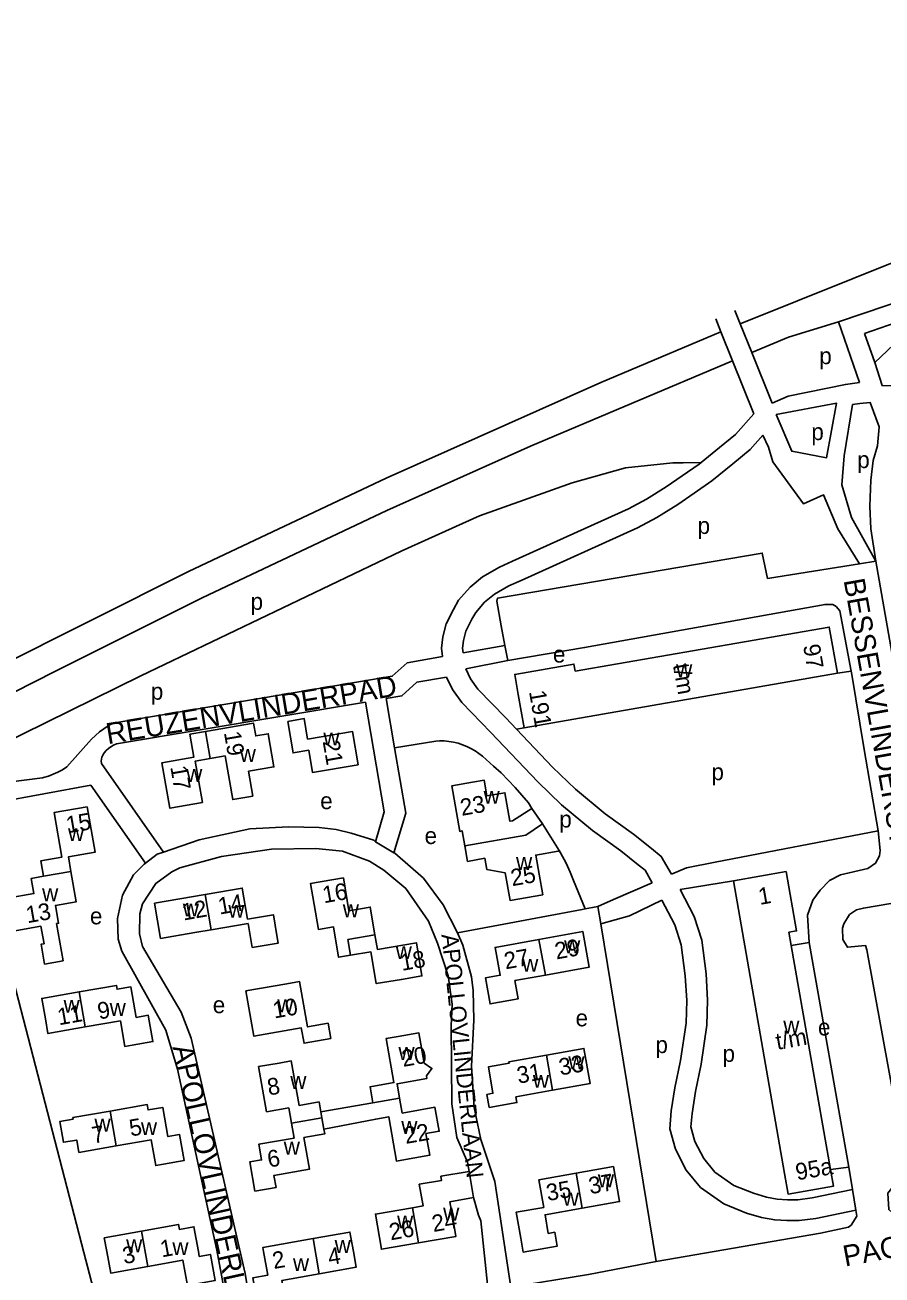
# Model space of a CAD drawing. Extents: x 162883 to 165538, y 383986 to 385172.
# Drawn here: x 164067.6 to 164272, y 384744.4 to 385042.6 of the extents above; entities that cross this region are included whole.
import ezdxf

# ---------------------------------------------------------------- set-up
doc = ezdxf.new("R2010")
doc.units = 0
for name, color, linetype in [('BLT_Basislijn', 7, 'Continuous'), ('BLT_Bebouwing', 7, 'Continuous'), ('BLT_Centroide', 7, 'Continuous'), ('BLT_Huisnummer', 7, 'Continuous'), ('BLT_Huisnummer_reeks', 7, 'Continuous'), ('BLT_Onderverdeling_panden', 7, 'Continuous'), ('BLT_Straatnaam', 7, 'Continuous'), ('BLT_Straatnaam_verkleind', 7, 'Continuous')]:
    doc.layers.add(name, color=color, linetype=linetype)

msp = doc.modelspace()

# ---------------------------------------------------------------- linework, layer by layer
at = {"layer": 'BLT_Basislijn'}
for p, q in [((164283.76, 384989.59), (164238.23, 384971.28)), ((164261.66, 384971.76), (164292.03, 384982.1)), ((164267.9, 384969), (164293.76, 384977.99)), ((164236.95, 384974.46), (164238.23, 384971.28)), ((164232.37, 384972.46), (164233.62, 384969.34)), ((164238.23, 384971.28), (164241, 384964.41)), ((164261.66, 384971.76), (164266.65, 384957.28)), ((164233.62, 384969.34), (164236.39, 384962.47)), ((164267.9, 384969), (164270.29, 384962.05)), ((164241, 384964.41), (164245.86, 384952.35)), ((164236.39, 384962.47), (164241.49, 384949.82)), ((164249.61, 384954.04), (164245.86, 384952.35)), ((164224.6, 384938.13), (164228.89, 384938.23)), ((164181.18, 384899.24), (164182.09, 384894.57)), ((164182.09, 384894.57), (164182.8, 384890.95)), ((164182.8, 384890.95), (164172.75, 384888.98)), ((164261.38, 384887.91), (164264.67, 384888.42)), ((164089.39, 384871.05), (164148.83, 384881.06)), ((164153.76, 384881.89), (164155.76, 384870.14)), ((164186.63, 384874.92), (164184.82, 384874.62)), ((164083.46, 384872.22), (164077.55, 384865.57)), ((164165.57, 384871.74), (164155.76, 384870.14)), ((164085.84, 384866.36), (164100.62, 384845.25)), ((164083.31, 384861.25), (164054.09, 384855.8)), ((164071.72, 384862.98), (164063.65, 384861.95)), ((164083.31, 384861.25), (164096.35, 384842.63)), ((164054.09, 384855.8), (164081.63, 384749.74)), ((164099.12, 384844.73), (164100.62, 384845.25)), ((164151.18, 384847.74), (164155.61, 384845.09)), ((164155.61, 384845.09), (164155.77, 384845)), ((164096.35, 384842.63), (164095.97, 384842.34)), ((164099.12, 384844.73), (164096.35, 384842.63)), ((164198.45, 384838.51), (164201.18, 384831.69)), ((164236.57, 384838.38), (164223.85, 384836.3)), ((164200.54, 384831.57), (164170.73, 384825.96)), ((164200.54, 384831.57), (164201.18, 384831.69)), ((164201.18, 384831.69), (164202.97, 384832.01)), ((164202.97, 384832.01), (164204.28, 384832.24)), ((164204.95, 384828.17), (164204.28, 384832.24)), ((164218.19, 384747.63), (164204.95, 384828.17)), ((164254.66, 384823.68), (164250.38, 384822.96)), ((164254.66, 384823.68), (164264.11, 384770.12)), ((164264.11, 384770.12), (164259.78, 384769.55)), ((164081.63, 384749.74), (164088.15, 384724.64))]:
    msp.add_line(p, q, dxfattribs=at)
for points in [[(164490.02, 385042.56), (164488.13, 385042.29), (164422.4, 385021.48), (164377.6, 385005.76), (164289.97, 384972.55), (164276.26, 384967.72), (164270.29, 384962.05)], [(164261.66, 384971.76), (164249.74, 384968.11), (164241, 384964.41)], [(164233.62, 384969.34), (164204.95, 384957.3), (164153.73, 384934.44)], [(164270.29, 384962.05), (164272.06, 384956.53), (164277.96, 384956.41), (164284.23, 384957.02), (164288.93, 384957.86), (164294.36, 384959.07), (164300.27, 384960.39), (164302.8, 384961), (164305.69, 384961.96), (164308.34, 384963.17), (164315.2, 384968.2)], [(164236.39, 384962.47), (164188.18, 384942.07), (164153.89, 384926.74)], [(164249.61, 384954.04), (164263.32, 384956.83), (164266.65, 384957.28)], [(164266.73, 384952.25), (164269.25, 384952.47), (164271.36, 384946.68), (164270.94, 384942.16), (164269.95, 384938.64), (164269.39, 384933.98), (164269.11, 384927.77), (164269.39, 384922.41), (164270.57, 384914.65)], [(164228.89, 384938.23), (164233.27, 384941.76), (164237.09, 384944.88), (164241.49, 384949.82)], [(164270.57, 384914.65), (164264.73, 384925.09), (164262.48, 384932.85), (164263.04, 384939.77), (164265.02, 384952.01)], [(164265.02, 384952.01), (164266.73, 384952.25)], [(164172.1, 384892.8), (164171.98, 384893.88), (164172.18, 384895.71), (164172.78, 384897.93), (164174.21, 384900.79), (164175.14, 384902.45), (164177.24, 384904.87), (164179.58, 384906.78), (164183.02, 384908.78), (164185.92, 384910.05), (164213.74, 384922.64), (164218.34, 384925.1), (164223.32, 384928.19), (164227.24, 384930.89), (164231.41, 384933.84), (164236.43, 384937.87), (164240.56, 384941.26), (164243.63, 384944.7)], [(164243.63, 384944.7), (164244.99, 384941.88), (164245.97, 384938.35), (164253.31, 384928.33), (164258.1, 384930.45), (164261.49, 384922.41), (164266.7, 384914.03)], [(163832.96, 384744.27), (163844.99, 384751.02), (164038.65, 384858.43), (164038.88, 384858.81), (164039.72, 384859.01), (164061.27, 384870.58), (164095.24, 384887.32), (164157.3, 384917.02), (164176.04, 384925.47), (164198.09, 384933.36), (164210.88, 384936.92), (164222.14, 384938.13), (164224.6, 384938.13)], [(164167.16, 384891.92), (164166.96, 384893.88), (164167.24, 384896.64), (164168.09, 384899.72), (164169.79, 384903.14), (164171.03, 384905.34), (164173.75, 384908.47), (164176.72, 384910.9), (164180.75, 384913.24), (164183.88, 384914.62), (164211.52, 384927.12), (164215.84, 384929.44), (164220.58, 384932.38), (164224.38, 384934.99), (164228.4, 384937.83), (164228.89, 384938.23)], [(164153.73, 384934.44), (164106.58, 384912.17), (164059.88, 384888.8), (164044.54, 384881.09)], [(164153.89, 384926.74), (164109.86, 384905.93), (164074.69, 384888.33), (164050.32, 384876.05)], [(164181.18, 384899.24), (164180.15, 384905.12), (164180.31, 384905.87), (164243.47, 384916.58), (164244.74, 384910.51)], [(164244.74, 384910.51), (164266.7, 384914.03)], [(164266.7, 384914.03), (164270.57, 384914.65)], [(164277.93, 384872.45), (164270.57, 384914.65)], [(164264.67, 384888.42), (164261.94, 384902.78), (164261.08, 384903.83), (164260.31, 384904.29), (164258.44, 384904.34), (164201.09, 384894.06), (164182.8, 384890.95)], [(164172.1, 384892.8), (164182.09, 384894.57)], [(164088.56, 384875.98), (164155.21, 384887.2), (164158.76, 384890.43), (164167.16, 384891.92)], [(164153.76, 384881.89), (164157.49, 384882.51), (164161.06, 384885.76), (164168.15, 384887.02)], [(164168.15, 384887.02), (164169.54, 384884.07), (164171.77, 384880.94), (164178.69, 384873.82), (164189.9, 384862), (164195.59, 384856.5), (164202.93, 384850.39), (164209.73, 384845.58), (164213.87, 384842.23), (164215.51, 384840.92), (164217.23, 384837.96)], [(164172.75, 384888.98), (164173.87, 384886.61), (164175.62, 384884.15), (164182.29, 384877.28), (164184.82, 384874.62)], [(164267.82, 384869.77), (164264.74, 384888.08), (164264.67, 384888.42)], [(164148.83, 384881.06), (164153.3, 384854.86), (164151.18, 384847.74)], [(164088.56, 384875.98), (164087.45, 384875.36), (164086.38, 384874.67), (164085.36, 384873.92), (164084.39, 384873.1), (164083.46, 384872.22)], [(164184.82, 384874.62), (164193.45, 384865.52), (164198.93, 384860.23), (164205.98, 384854.36), (164212.75, 384849.57), (164217.01, 384846.13), (164219.36, 384844.24), (164221.85, 384839.97)], [(164089.39, 384871.05), (164088.72, 384870.76), (164088.08, 384870.39), (164087.49, 384869.96), (164086.95, 384869.47), (164086.47, 384868.93), (164086.38, 384868.81)], [(164155.76, 384870.14), (164158.42, 384854.56), (164155.61, 384845.09)], [(164177.56, 384867.37), (164176.74, 384868.12), (164175.86, 384868.8), (164174.94, 384869.43), (164173.98, 384869.99), (164172.98, 384870.47), (164171.95, 384870.88), (164170.89, 384871.22), (164169.81, 384871.48), (164168.71, 384871.66), (164167.61, 384871.76), (164166.5, 384871.79), (164165.57, 384871.74)], [(164271.09, 384850.3), (164267.82, 384869.77)], [(164086.38, 384868.81), (164086.12, 384868.39), (164085.92, 384867.94), (164085.81, 384867.46), (164085.77, 384866.97), (164085.81, 384866.47), (164085.84, 384866.36)], [(164177.56, 384867.37), (164179.38, 384865.78), (164181.16, 384864.13), (164182.88, 384862.43), (164184.54, 384860.67), (164186.14, 384858.85), (164187.69, 384856.99), (164188.47, 384855.69)], [(164077.55, 384865.57), (164076.51, 384864.92), (164075.43, 384864.34), (164074.31, 384863.84), (164073.16, 384863.4), (164071.98, 384863.05), (164071.72, 384862.98)], [(164100.62, 384845.25), (164109.16, 384848.22), (164121.25, 384850.78), (164130.42, 384851.26), (164137.74, 384851.14), (164141.78, 384850.62), (164145.43, 384849.75), (164150.76, 384848.08), (164151.18, 384847.74)], [(164232.22, 384842.82), (164271.09, 384850.3)], [(164254.66, 384823.68), (164254.29, 384830.21), (164255.52, 384833.76), (164257.26, 384836.18), (164259.49, 384838.45), (164262.1, 384839.82), (164268.62, 384841.31), (164270.47, 384842.58), (164271.42, 384844.33), (164271.58, 384845.67), (164271.09, 384850.3)], [(164173.52, 384769.06), (164173.14, 384771.32), (164170.63, 384777.21), (164169.37, 384785.24), (164169.21, 384803.85), (164169.45, 384808.94), (164168.57, 384815.72), (164165.99, 384823.55), (164163.88, 384828.74), (164158.47, 384836.54), (164153.16, 384840.98), (164149.79, 384843.12), (164143.36, 384845.45), (164136.93, 384846.08), (164126.4, 384845.93), (164114.47, 384844.18), (164104.55, 384841.47), (164102.57, 384840.52), (164098.82, 384837.78), (164095.64, 384832.88), (164095, 384830.49), (164094.89, 384825.75), (164095.64, 384822.7), (164104.8, 384807.05), (164107.25, 384800.9), (164120.14, 384744.7), (164122.44, 384730.7)], [(164195, 384845.62), (164195.32, 384845.05), (164196.65, 384842.65), (164197.65, 384840.44), (164198.45, 384838.51)], [(164095.97, 384842.34), (164093.47, 384839.82), (164090.83, 384834.95), (164089.67, 384829.38), (164089.81, 384824.45), (164090.64, 384821.59), (164101.2, 384802.81), (164103.99, 384793.49), (164113.36, 384750.3), (164117.16, 384729.76), (164088.15, 384724.64)], [(164170.73, 384825.96), (164167.31, 384832.71), (164162.62, 384839.05), (164155.77, 384845)], [(164221.85, 384839.97), (164225.38, 384841.5), (164232.22, 384842.82)], [(164204.28, 384832.24), (164207.96, 384833.94), (164217.23, 384837.96)], [(164223.85, 384836.3), (164227.23, 384829.87), (164229.05, 384824.24), (164230.09, 384816.19), (164230.44, 384809.94), (164230.27, 384803.98), (164228.89, 384794.69), (164227.55, 384788.13), (164226.73, 384782.89), (164226.44, 384779.73), (164227.42, 384776.22), (164229.54, 384772.14), (164232.18, 384768.91), (164236.69, 384765.75), (164241.36, 384763.88), (164244.47, 384762.95), (164247.04, 384762.49), (164249.51, 384762.34), (164251.95, 384762.34), (164255.39, 384762.81), (164264.98, 384764.78)], [(164219.51, 384833.82), (164211.82, 384830.07), (164204.95, 384828.17)], [(164219.51, 384833.82), (164222.6, 384827.93), (164224.15, 384823.14), (164225.11, 384815.73), (164225.44, 384809.88), (164225.28, 384804.42), (164223.96, 384795.56), (164222.62, 384789.01), (164221.76, 384783.5), (164221.38, 384779.27), (164222.75, 384774.38), (164225.34, 384769.38), (164228.74, 384765.21), (164234.3, 384761.32), (164239.71, 384759.16), (164243.31, 384758.07), (164246.45, 384757.52), (164249.36, 384757.34), (164252.29, 384757.34), (164256.24, 384757.88), (164265.78, 384759.84)], [(164283.48, 384834.6), (164267.61, 384831.89), (164265.95, 384831.5), (164264.26, 384830.34), (164262.93, 384828.17), (164262.65, 384827.11), (164262.71, 384824.37), (164263.8, 384822.54), (164268.11, 384822.94), (164268.43, 384821.96), (164277.4, 384772.74), (164278.33, 384766.16), (164274.67, 384765.52), (164273.43, 384763.9), (164273.65, 384759.96), (164275.72, 384758.07), (164277.4, 384757.88), (164284.57, 384759.39)], [(164218.19, 384747.63), (164202, 384744.49), (164183.49, 384741.49), (164179.63, 384766.7), (164176.36, 384776.66), (164174.75, 384784.35), (164174.11, 384794.16), (164174.69, 384805.19), (164174.5, 384812.21), (164174.11, 384815.48), (164172.03, 384823.03), (164170.73, 384825.96)], [(164264.98, 384764.78), (164264.11, 384770.12)], [(164265.78, 384759.84), (164264.98, 384764.78)], [(164178.07, 384740.58), (164176.29, 384757.32), (164175.74, 384758.62), (164174.58, 384762.82)], [(164218.19, 384747.63), (164257.4, 384754.38), (164264.02, 384755.75), (164264.68, 384756.27), (164266.01, 384758.43), (164265.78, 384759.84)]]:
    msp.add_lwpolyline(points, dxfattribs=at)
msp.add_lwpolyline([(164246.82, 384949.64), (164250.49, 384940.89), (164258.81, 384939.34), (164261.21, 384952.33)], close=True, dxfattribs=at)
at = {"layer": 'BLT_Bebouwing'}
for p, q in [((164110.63, 384874.06), (164106.9, 384873.41)), ((164188.47, 384855.69), (164191.06, 384852.01)), ((164191.06, 384852.01), (164195, 384845.62)), ((164259.78, 384769.55), (164250.38, 384822.96)), ((164138.17, 384783.26), (164150.57, 384785.42)), ((164174.58, 384762.82), (164173.52, 384769.06))]:
    msp.add_line(p, q, dxfattribs=at)
for points in [[(164186.63, 384874.92), (164185.23, 384882.83), (164184.41, 384887.63), (164198.55, 384890.09), (164198.84, 384888.42), (164259.45, 384898.95), (164261.38, 384887.91)], [(164186.63, 384874.92), (164261.38, 384887.91)], [(164121.93, 384858.6), (164120.9, 384864.54), (164126.97, 384865.59), (164125.59, 384873.5), (164122.63, 384872.99), (164122.09, 384876.05), (164110.63, 384874.06)], [(164130.26, 384876.43), (164134.18, 384877.09), (164135, 384872.21), (164145.71, 384874.02), (164147.05, 384866.09), (164136.15, 384864.26), (164135.26, 384869.54), (164131.52, 384868.91), (164130.26, 384876.43)], [(164106.9, 384873.41), (164107.86, 384867.91), (164100.26, 384866.59), (164102.15, 384855.73), (164109.92, 384857.09), (164108.2, 384866.96), (164111.76, 384867.58)], [(164111.76, 384867.58), (164115.31, 384868.2), (164117.13, 384857.77), (164121.93, 384858.6)], [(164172.52, 384846.75), (164171.9, 384850.3), (164171.3, 384850.2), (164169.4, 384861.04), (164174.33, 384861.9), (164177.14, 384862.39), (164177.78, 384858.68), (164182.08, 384859.43), (164183.27, 384852.62), (164183.91, 384852.73), (164188.47, 384855.69)], [(164072.02, 384839.5), (164071.37, 384843.2), (164076.38, 384844.08), (164074.52, 384854.68), (164082.39, 384856.05), (164084.29, 384845.23), (164077.94, 384844.12), (164078.55, 384840.65)], [(164177.3, 384843.77), (164173.17, 384843.05), (164172.52, 384846.75)], [(164195, 384845.62), (164194.8, 384845.5), (164189.42, 384844.56), (164190.21, 384840.01), (164191.08, 384835.08), (164183.31, 384833.73), (164182.17, 384840.27), (164177.77, 384841.09), (164177.3, 384843.77)], [(164078.55, 384840.65), (164079.82, 384833.41), (164074.84, 384832.54), (164075.59, 384828.29), (164075.13, 384828.21), (164076.68, 384819.34), (164072.23, 384818.56), (164071.4, 384823.28), (164072.11, 384823.4), (164071.39, 384827.56), (164064.75, 384826.4), (164063.38, 384834.25), (164069.71, 384835.36), (164069.07, 384838.99), (164072.02, 384839.5)], [(164236.57, 384838.38), (164249.15, 384840.6), (164251.64, 384826.44), (164249.82, 384826.13), (164250.38, 384822.96)], [(164112, 384826.72), (164120.81, 384828.22), (164121.78, 384822.5), (164127.99, 384823.56), (164127.67, 384825.38), (164126.83, 384830.31), (164120.68, 384829.26), (164119.4, 384836.69), (164110.56, 384835.18)], [(164145.26, 384820.64), (164142.4, 384820.16), (164141.18, 384827.41), (164137.56, 384826.8), (164136.55, 384832.79), (164135.71, 384837.77), (164143.55, 384839.09), (164144.86, 384831.27), (164149.95, 384832.13), (164151.06, 384825.54)], [(164259.78, 384769.55), (164260.48, 384765.57), (164249.64, 384763.66), (164248.78, 384768.59), (164236.57, 384838.38)], [(164110.56, 384835.18), (164098.45, 384833.11)], [(164098.45, 384833.11), (164099.87, 384824.64)], [(164099.87, 384824.64), (164108.08, 384826.04), (164112, 384826.72)], [(164151.06, 384825.54), (164151.65, 384822.06), (164160.96, 384823.62), (164162.29, 384815.72), (164157.36, 384814.89), (164151.38, 384813.88), (164150.11, 384821.46), (164145.26, 384820.64)], [(164190.19, 384824.41), (164179.74, 384822.5), (164180.95, 384815.87), (164177.43, 384815.23), (164178.55, 384809.05), (164185.26, 384810.27), (164184.47, 384814.59), (164191.74, 384815.92)], [(164191.74, 384815.92), (164202.19, 384817.82), (164200.64, 384826.32), (164190.19, 384824.41)], [(164081.95, 384803.54), (164090.32, 384805), (164091.38, 384798.9), (164093.16, 384799.21), (164098.08, 384800.07), (164096.99, 384806.33), (164094.11, 384805.83), (164092.84, 384813.1), (164089.54, 384812.52), (164089.38, 384813.47), (164080.48, 384811.91)], [(164140.54, 384800.79), (164139.9, 384804.43), (164134.98, 384803.57), (164133.08, 384814.38), (164130.07, 384813.85), (164120.27, 384812.13), (164122.17, 384801.31), (164133.49, 384803.31), (164134.14, 384799.66), (164140.54, 384800.79)], [(164080.48, 384811.91), (164071.59, 384810.36), (164072.45, 384805.45), (164073.06, 384801.98), (164081.95, 384803.54)], [(164150.57, 384785.42), (164149.9, 384789.26), (164155.59, 384790.26), (164153.74, 384800.77), (164156.62, 384801.28), (164161.54, 384802.14), (164162.81, 384794.91), (164164.65, 384793.66), (164163.34, 384791.9), (164163.46, 384791.26), (164156.35, 384790.01), (164156.96, 384786.54)], [(164193.46, 384788.43), (164202.41, 384790.03), (164200.92, 384798.43), (164191.97, 384796.83)], [(164131.14, 384780.57), (164130.49, 384784.23), (164125.2, 384783.3), (164123.31, 384794.08), (164128.21, 384794.94), (164131.1, 384795.45), (164132.97, 384784.83), (164137.75, 384785.67), (164138.17, 384783.26)], [(164191.97, 384796.83), (164183.02, 384795.24), (164183.08, 384794.9), (164178.13, 384794.02), (164179.21, 384787.72), (164177.77, 384787.46), (164178.32, 384784.36), (164184.95, 384785.51), (164184.71, 384786.87), (164193.46, 384788.43)], [(164156.96, 384786.54), (164157.58, 384783), (164165.39, 384784.37), (164166.39, 384778.66), (164163.22, 384778.11), (164164.12, 384772.95), (164159.2, 384772.09), (164156.2, 384771.56), (164154.34, 384782.12), (164151.25, 384781.58), (164138.89, 384779.15)], [(164087.86, 384783.47), (164078.99, 384781.94), (164079.05, 384781.57), (164075.89, 384781.02), (164076.75, 384776.02), (164079.92, 384776.56), (164080.42, 384773.63), (164089.3, 384775.16)], [(164089.3, 384775.16), (164097.71, 384776.61), (164098.76, 384770.48), (164100.6, 384770.8), (164105.53, 384771.65), (164104.46, 384777.86), (164101.66, 384777.38), (164100.42, 384784.36), (164096.96, 384783.76), (164096.74, 384785.01), (164087.86, 384783.47)], [(164138.89, 384779.15), (164139.09, 384778.02), (164134.12, 384777.15), (164135.45, 384769.6), (164126.97, 384768.11), (164127.47, 384765.25), (164122.43, 384764.37), (164121.21, 384771.34), (164124, 384771.83), (164123.35, 384775.58), (164131.76, 384777.05), (164131.14, 384780.57)], [(164173.52, 384769.06), (164166.81, 384767.92), (164166.97, 384766.94), (164161.65, 384766.01), (164162.53, 384760.84), (164160.06, 384760.42)], [(164185.84, 384753.14), (164184.74, 384759.33), (164191.35, 384760.5), (164190.18, 384767.11), (164199.06, 384768.68)], [(164199.06, 384768.68), (164207.94, 384770.25), (164209.42, 384761.9), (164200.54, 384760.32)], [(164161.48, 384752.04), (164170.36, 384753.55), (164169.62, 384757.91), (164168.94, 384761.86), (164174.58, 384762.82)], [(164160.06, 384760.42), (164151.19, 384758.92), (164152.61, 384750.53), (164161.48, 384752.04)], [(164200.54, 384760.32), (164191.64, 384758.75), (164192.43, 384754.31)], [(164108.94, 384750), (164107.87, 384755.87), (164104.43, 384755.24), (164104.21, 384756.43), (164095.36, 384754.82)], [(164095.36, 384754.82), (164086.5, 384753.2), (164087.09, 384750)], [(164136.32, 384753.07), (164124.32, 384750.96), (164124.49, 384750)], [(164145.92, 384750), (164145.11, 384754.61), (164136.32, 384753.07)], [(164192.43, 384754.31), (164193.98, 384754.58), (164194.57, 384751.28), (164186.42, 384749.84), (164185.84, 384753.14)], [(164096.89, 384746.43), (164088.02, 384744.81), (164087.09, 384750)], [(164108.94, 384750), (164109.14, 384748.81), (164111.8, 384749.3), (164112.94, 384743.05), (164106.32, 384741.84), (164105.2, 384747.94), (164096.89, 384746.43)], [(164124.49, 384750), (164125.5, 384744.36), (164121.94, 384743.73), (164123.03, 384737.53), (164129.65, 384738.69), (164128.88, 384743.09), (164137.78, 384744.66)], [(164137.78, 384744.66), (164146.58, 384746.21), (164145.92, 384750)]]:
    msp.add_lwpolyline(points, dxfattribs=at)
at = {"layer": 'BLT_Onderverdeling_panden'}
for p, q in [((164111.76, 384867.58), (164110.63, 384874.06)), ((164072.02, 384839.5), (164078.55, 384840.65)), ((164110.56, 384835.18), (164112, 384826.72)), ((164190.19, 384824.41), (164191.74, 384815.92)), ((164080.48, 384811.91), (164081.95, 384803.54)), ((164191.97, 384796.83), (164193.46, 384788.43)), ((164150.57, 384785.42), (164156.96, 384786.54)), ((164087.86, 384783.47), (164089.3, 384775.16)), ((164138.17, 384783.26), (164138.42, 384781.85)), ((164138.42, 384781.85), (164131.14, 384780.57)), ((164138.42, 384781.85), (164138.89, 384779.15)), ((164199.06, 384768.68), (164200.54, 384760.32)), ((164161.48, 384752.04), (164160.06, 384760.42)), ((164095.36, 384754.82), (164096.89, 384746.43)), ((164136.32, 384753.07), (164137.78, 384744.66))]:
    msp.add_line(p, q, dxfattribs=at)
for points in [[(164191.06, 384852.01), (164187.03, 384849.26), (164172.52, 384846.75)], [(164145.26, 384820.64), (164144.6, 384824.39), (164151.06, 384825.54)]]:
    msp.add_lwpolyline(points, dxfattribs=at)

# ---------------------------------------------------------------- texts
at = {"layer": 'BLT_Centroide'}
for s, p in [('p', (164257.08, 384961.64)), ('p', (164255.18, 384943.53)), ('p', (164266.13, 384936.86)), ('p', (164228.04, 384921.15)), ('p', (164121.4, 384903.05)), ('e', (164193.53, 384890.47)), ('w', (164222.91, 384886.94)), ('p', (164097.6, 384881.61)), ('w', (164138.76, 384870.69)), ('w', (164118.8, 384866.77)), ('w', (164106.02, 384862)), ('p', (164231.35, 384862.4)), ('e', (164138, 384855.5)), ('w', (164176.98, 384856.78)), ('p', (164195.05, 384851.12)), ('w', (164077.83, 384847.89)), ('e', (164162.91, 384847.18)), ('w', (164184.72, 384840.98)), ('w', (164071.65, 384833.53)), ('e', (164083.07, 384828.02)), ('w', (164105.22, 384829.91)), ('w', (164116.07, 384829.59)), ('w', (164143.39, 384829.7)), ('w', (164156.02, 384819.72)), ('w', (164196.19, 384821.12)), ('w', (164186.19, 384816.72)), ('w', (164076.77, 384806.94)), ('e', (164112.37, 384806.83)), ('w', (164127.77, 384807.03)), ('w', (164087.77, 384806.19)), ('e', (164198.93, 384803.69)), ('w', (164248.48, 384801.98)), ('e', (164256.76, 384801.51)), ('p', (164217.99, 384797.31)), ('w', (164156.67, 384795.67)), ('p', (164233.99, 384795.21)), ('w', (164197.2, 384793.44)), ('w', (164130.86, 384788.77)), ('w', (164188.74, 384789.03)), ('w', (164084.15, 384778.56)), ('w', (164095.23, 384777.75)), ('w', (164157.34, 384778.03)), ('w', (164129.3, 384773.09)), ('w', (164204.24, 384765.28)), ('w', (164195.86, 384760.91)), ('w', (164167.33, 384757.34)), ('w', (164156.34, 384755.47)), ('w', (164091.7, 384749.81)), ('w', (164141.45, 384749.62)), ('w', (164102.73, 384749.12)), ('w', (164131.5, 384745.31))]:
    msp.add_text(s, height=4, dxfattribs=at).set_placement(p)
at = {"layer": 'BLT_Huisnummer'}
for s, rotation, p in [('19', 279.8703, (164115.02, 384873.78)), ('21', 279.8703, (164138.58, 384871.64)), ('17', 279.8703, (164102.23, 384865.58)), ('23', 9.9308, (164171.77, 384853.89)), ('15', 9.9173, (164077.72, 384849.72)), ('25', 9.9212, (164183.81, 384837.11)), ('16', 9.9842, (164138.9, 384833.04)), ('12', 9.9842, (164105.39, 384828.92)), ('14', 9.9842, (164114, 384830.34)), ('13', 9.9162, (164068.15, 384828.28)), ('29', 10.3384, (164194.34, 384819.63)), ('18', 9.9842, (164157.51, 384816.91)), ('27', 10.3384, (164182.23, 384817.27)), ('9', 9.9074, (164085.24, 384805.31)), ('10', 9.9842, (164127.06, 384805.55)), ('11', 9.9074, (164075.67, 384803.93)), ('20', 9.9842, (164157.8, 384794)), ('31', 10.1102, (164185.28, 384789.99)), ('33', 10.1102, (164195.31, 384791.95)), ('8', 9.9842, (164125.74, 384787.17)), ('7', 9.7964, (164083.89, 384775.7)), ('5', 9.7964, (164092.8, 384777.4)), ('22', 9.9842, (164158.43, 384775.63)), ('6', 9.9842, (164125.76, 384769.98)), ('37', 10.0253, (164202.42, 384763.63)), ('35', 10.0253, (164192.29, 384761.99)), ('24', 9.9842, (164165.01, 384754.61)), ('26', 9.9842, (164154.82, 384752.63)), ('1', 10.3374, (164100.2, 384748.56)), ('3', 10.3374, (164091.22, 384746.95)), ('2', 9.9842, (164126.95, 384745.79)), ('4', 9.9842, (164140.19, 384746.66))]:
    msp.add_text(s, height=4, rotation=rotation, dxfattribs=at).set_placement(p)
at = {"layer": 'BLT_Huisnummer_reeks'}
for s, rotation, p in [('97', 279.8788, (164253.2, 384894.53)), ('t/m', 279.878, (164222.16, 384889.91)), ('191', 279.8803, (164187.81, 384883.54)), ('1', 9.9829, (164242.9, 384832.65)), ('t/m', 9.9796, (164247.06, 384798.07)), ('95a', 9.9838, (164251.77, 384766.94))]:
    msp.add_text(s, height=4, rotation=rotation, dxfattribs=at).set_placement(p)
at = {"layer": 'BLT_Straatnaam'}
for s, rotation, p in [('BESSENVLINDERSTRAAT', 280.1002, (164262.86, 384910.12)), ('REUZENVLINDERPAD', 9.5237, (164087.34, 384870.98)), ('APOLLOVLINDERLAAN', 282.4461, (164102.74, 384798.76)), ('PAGELAAN', 10.5729, (164263.22, 384746.36))]:
    msp.add_text(s, height=5, rotation=rotation, dxfattribs=at).set_placement(p)
at = {"layer": 'BLT_Straatnaam_verkleind'}
msp.add_text('APOLLOVLINDERLAAN', height=4, rotation=275.9869, dxfattribs=at).set_placement((164166.92, 384825.57))

doc.saveas('drawing.dxf')
